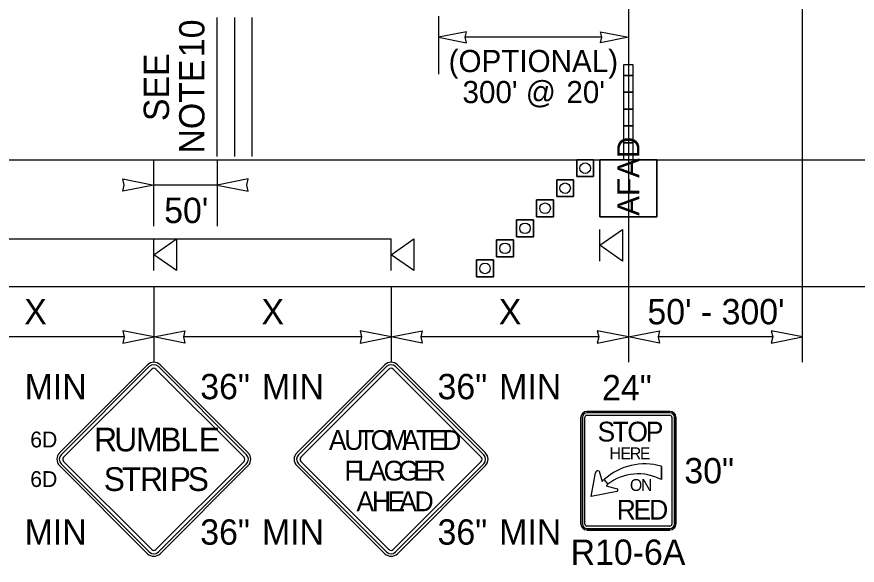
# Model space of a CAD drawing. Extents: x 99999.1 to 100095.7, y 99995 to 100010.7.
# Drawn here: x 100002.344 to 100005, y 100004.851 to 100006.584 of the extents above; entities that cross this region are included whole.
import ezdxf

# ---------------------------------------------------------------- set-up
doc = ezdxf.new("R2010")
doc.units = 0
for name, color, linetype in [('RD_ED_ShoulderPavedEdge', 7, 'Continuous'), ('RD_MK_LineEdgeWhite', 7, 'Continuous'), ('TR_SN_ConstructionSigns', 7, 'Continuous'), ('TR_WZ_AFAD', 7, 'Continuous'), ('TR_WZ_PortableSignMountBlk-Org', 7, 'Continuous'), ('TR_WZ_PortableSignMountBlk-Wht', 7, 'Continuous'), ('TR_WZ_TrafficCone', 7, 'Continuous'), ('TR_WZ_WorkZoneDetails', 7, 'Continuous'), ('TR_WZ_WorkZoneTextCurrent', 7, 'Continuous')]:
    doc.layers.add(name, color=color, linetype=linetype)

msp = doc.modelspace()

# ---------------------------------------------------------------- linework, layer by layer
at = {"layer": 'RD_ED_ShoulderPavedEdge'}
msp.add_line((100000.1076, 100005.7323), (100015.6424, 100005.7323), dxfattribs=at)
at = {"layer": 'RD_MK_LineEdgeWhite'}
msp.add_line((100000.1076, 100006.1323), (100015.6424, 100006.1323), dxfattribs=at)
at = {"layer": 'TR_SN_ConstructionSigns'}
for p, q in [((100002.7568, 100005.4841), (100002.4783, 100005.2057)), ((100002.7623, 100005.4786), (100002.4839, 100005.2001)), ((100002.4916, 100005.1924), (100002.77, 100005.4708)), ((100002.7833, 100005.4708), (100003.0617, 100005.1924)), ((100003.0694, 100005.2001), (100002.791, 100005.4786)), ((100003.075, 100005.2057), (100002.7965, 100005.4841)), ((100003.5068, 100005.4841), (100003.2283, 100005.2057)), ((100003.5123, 100005.4786), (100003.2339, 100005.2001)), ((100003.2416, 100005.1924), (100003.52, 100005.4708)), ((100003.5333, 100005.4708), (100003.8117, 100005.1924)), ((100003.8194, 100005.2001), (100003.541, 100005.4786)), ((100003.825, 100005.2057), (100003.5465, 100005.4841)), ((100004.4079, 100005.3373), (100004.1454, 100005.3373)), ((100004.1454, 100005.3373), (100004.4079, 100005.3373)), ((100004.4079, 100005.3373), (100004.1454, 100005.3373)), ((100004.1454, 100005.3373), (100004.4079, 100005.3373)), ((100004.4079, 100005.3326), (100004.1454, 100005.3326)), ((100004.1267, 100005.3186), (100004.1267, 100004.9811)), ((100004.1267, 100004.9811), (100004.1267, 100005.3186)), ((100004.1267, 100005.3186), (100004.1267, 100004.9811)), ((100004.1267, 100004.9811), (100004.1267, 100005.3186)), ((100004.1313, 100005.3186), (100004.1313, 100004.9811)), ((100004.1392, 100004.9811), (100004.1392, 100005.3186)), ((100004.1454, 100005.3248), (100004.4079, 100005.3248)), ((100004.4142, 100005.3186), (100004.4142, 100004.9811)), ((100004.422, 100004.9811), (100004.422, 100005.3186)), ((100004.4267, 100004.9811), (100004.4267, 100005.3186)), ((100004.4267, 100005.3186), (100004.4267, 100004.9811)), ((100004.4267, 100004.9811), (100004.4267, 100005.3186)), ((100004.4267, 100005.3186), (100004.4267, 100004.9811)), ((100002.4839, 100005.1714), (100002.7623, 100004.893)), ((100002.77, 100004.9007), (100002.4916, 100005.1792)), ((100003.0617, 100005.1792), (100002.7833, 100004.9007)), ((100002.791, 100004.893), (100003.0694, 100005.1714)), ((100003.2339, 100005.1714), (100003.5123, 100004.893)), ((100003.52, 100004.9007), (100003.2416, 100005.1792)), ((100003.8117, 100005.1792), (100003.5333, 100004.9007)), ((100003.541, 100004.893), (100003.8194, 100005.1714)), ((100002.4783, 100005.1659), (100002.7568, 100004.8875)), ((100002.7965, 100004.8875), (100003.075, 100005.1659)), ((100003.2283, 100005.1659), (100003.5068, 100004.8875)), ((100003.5465, 100004.8875), (100003.825, 100005.1659)), ((100004.1595, 100005.0686), (100004.1731, 100005.143)), ((100004.1839, 100005.1479), (100004.1933, 100005.1154)), ((100004.3816, 100005.1635), (100004.3813, 100005.1216)), ((100004.3813, 100005.1216), (100004.3816, 100005.1635)), ((100004.1933, 100005.1154), (100004.1996, 100005.1218)), ((100004.1996, 100005.1218), (100004.2113, 100005.1069)), ((100004.1996, 100005.1218), (100004.2113, 100005.1069)), ((100004.2113, 100005.1069), (100004.2066, 100005.1021)), ((100004.2066, 100005.1021), (100004.2408, 100005.0929)), ((100004.2406, 100005.0837), (100004.1595, 100005.0686)), ((100004.4079, 100004.9748), (100004.1454, 100004.9748)), ((100004.1454, 100004.967), (100004.4079, 100004.967)), ((100004.1454, 100004.9623), (100004.4079, 100004.9623)), ((100004.4079, 100004.9623), (100004.1454, 100004.9623)), ((100004.1454, 100004.9623), (100004.4079, 100004.9623)), ((100004.4079, 100004.9623), (100004.1454, 100004.9623))]:
    msp.add_line(p, q, dxfattribs=at)
for centre, radius, start, end in [((100002.7767, 100005.4642), 0.0281, 45, 135), ((100003.5267, 100005.4642), 0.0281, 45, 135), ((100002.7767, 100005.4642), 0.0203, 45, 135), ((100002.7767, 100005.4642), 0.00937, 45, 135), ((100003.5267, 100005.4642), 0.0203, 45, 135), ((100003.5267, 100005.4642), 0.00937, 45, 135), ((100004.1454, 100005.3186), 0.0187, 90, 180), ((100004.1454, 100005.3186), 0.0187, 90, 180), ((100004.1454, 100005.3186), 0.0187, 90, 180), ((100004.1454, 100005.3186), 0.0187, 90, 180), ((100004.1454, 100005.3186), 0.0141, 90, 180), ((100004.4079, 100005.3186), 0.0187, 0, 90), ((100004.4079, 100005.3186), 0.0187, 0, 90), ((100004.4079, 100005.3186), 0.0187, 0, 90), ((100004.4079, 100005.3186), 0.0187, 0, 90), ((100004.4079, 100005.3186), 0.0141, 0, 90), ((100004.1454, 100005.3186), 0.00625, 90, 180), ((100004.4079, 100005.3186), 0.00625, 0, 90), ((100002.4982, 100005.1858), 0.0281, 135, 225), ((100002.4982, 100005.1858), 0.0203, 135, 225), ((100003.0551, 100005.1858), 0.0203, 315, 45), ((100003.0551, 100005.1858), 0.0281, 315, 45), ((100003.2482, 100005.1858), 0.0281, 135, 225), ((100003.2482, 100005.1858), 0.0203, 135, 225), ((100003.8051, 100005.1858), 0.0203, 315, 45), ((100003.8051, 100005.1858), 0.0281, 315, 45), ((100002.4982, 100005.1858), 0.00937, 135, 225), ((100003.0551, 100005.1858), 0.00937, 315, 45), ((100003.2482, 100005.1858), 0.00937, 135, 225), ((100003.8051, 100005.1858), 0.00937, 315, 45), ((100004.3279, 100004.9804), 0.1909, 73.6434, 132.2131), ((100004.3279, 100004.9804), 0.1909, 73.6434, 132.2131), ((100004.3078, 100004.981), 0.1586, 62.4149, 127.4769), ((100004.3078, 100004.981), 0.1586, 62.4149, 127.4769), ((100004.1454, 100004.9811), 0.0187, 180, 270), ((100004.1454, 100004.9811), 0.0187, 180, 270), ((100004.1454, 100004.9811), 0.0187, 180, 270), ((100004.1454, 100004.9811), 0.0187, 180, 270), ((100004.1454, 100004.9811), 0.0141, 180, 270), ((100004.1454, 100004.9811), 0.00625, 180, 270), ((100004.4079, 100004.9811), 0.0187, 270, 0), ((100004.4079, 100004.9811), 0.0187, 270, 0), ((100004.4079, 100004.9811), 0.0187, 270, 0), ((100004.4079, 100004.9811), 0.0141, 270, 0), ((100004.4079, 100004.9811), 0.00625, 270, 0), ((100004.4079, 100004.9811), 0.0187, 270, 0), ((100002.7767, 100004.9074), 0.0281, 225, 315), ((100002.7767, 100004.9074), 0.0203, 225, 315), ((100002.7767, 100004.9074), 0.00937, 225, 315), ((100003.5267, 100004.9074), 0.0281, 225, 315), ((100003.5267, 100004.9074), 0.0203, 225, 315), ((100003.5267, 100004.9074), 0.00937, 225, 315)]:
    msp.add_arc(centre, radius, start, end, dxfattribs=at)
for centre, major_axis, ratio, start_param, end_param in [((100004.1795, 100005.1431), (-0.00647, -0.00009), 0.989437, 3.962549, 6.283185), ((100004.2384, 100005.0883), (-0.0046, 0.00239), 0.999053, 2.490568, 4.712389)]:
    msp.add_ellipse(centre, major_axis=major_axis, ratio=ratio, start_param=start_param, end_param=end_param, dxfattribs=at)
at = {"layer": 'TR_WZ_AFAD'}
for p, q in [((100004.2916, 100006.399), (100004.2916, 100006.4323)), ((100004.2616, 100006.399), (100004.2616, 100006.3457)), ((100004.2616, 100006.399), (100004.2766, 100006.399)), ((100004.2766, 100006.399), (100004.2916, 100006.399)), ((100004.2916, 100006.3457), (100004.2916, 100006.399)), ((100004.2616, 100006.3457), (100004.2616, 100006.2923)), ((100004.2766, 100006.3457), (100004.2616, 100006.3457)), ((100004.2916, 100006.3457), (100004.2766, 100006.3457)), ((100004.2916, 100006.2923), (100004.2916, 100006.3457)), ((100004.2616, 100006.2923), (100004.2616, 100006.239)), ((100004.2616, 100006.2923), (100004.2766, 100006.2923)), ((100004.2766, 100006.2923), (100004.2916, 100006.2923)), ((100004.2916, 100006.239), (100004.2916, 100006.2923)), ((100004.2766, 100006.239), (100004.2616, 100006.239)), ((100004.2616, 100006.239), (100004.2616, 100006.1857)), ((100004.2916, 100006.239), (100004.2766, 100006.239)), ((100004.2916, 100006.1857), (100004.2916, 100006.239)), ((100004.2616, 100006.1857), (100004.2616, 100006.1323)), ((100004.1866, 100005.9523), (100004.1866, 100006.1323)), ((100004.1866, 100006.1323), (100004.3666, 100006.1323)), ((100004.27, 100006.1323), (100004.1866, 100006.1323)), ((100004.1866, 100006.1323), (100004.1866, 100005.9523)), ((100004.2616, 100006.1323), (100004.27, 100006.1323)), ((100004.27, 100006.1323), (100004.2766, 100006.1323)), ((100004.3666, 100006.1323), (100004.3666, 100005.9523)), ((100004.3666, 100005.9523), (100004.3666, 100006.1323)), ((100004.3666, 100005.9523), (100004.1866, 100005.9523)), ((100004.1866, 100005.9523), (100004.3666, 100005.9523))]:
    msp.add_line(p, q, dxfattribs=at)
for points in [[(100004.2916, 100006.4323), (100004.2616, 100006.4323), (100004.2616, 100006.399)], [(100004.2916, 100006.1323), (100004.2916, 100006.4323), (100004.2616, 100006.4323), (100004.2616, 100006.1323)], [(100004.2916, 100006.399), (100004.2766, 100006.399), (100004.2616, 100006.399)], [(100004.2616, 100006.3457), (100004.2766, 100006.3457), (100004.2916, 100006.3457)], [(100004.2916, 100006.2923), (100004.2766, 100006.2923), (100004.2616, 100006.2923)], [(100004.2616, 100006.239), (100004.2766, 100006.239), (100004.2916, 100006.239)], [(100004.2916, 100006.1857), (100004.2766, 100006.1857), (100004.2616, 100006.1857)], [(100004.2616, 100006.1857), (100004.2766, 100006.1857), (100004.2916, 100006.1857)], [(100004.2766, 100006.1323), (100004.2833, 100006.1323), (100004.2916, 100006.1323), (100004.2916, 100006.1857)], [(100004.3666, 100006.1323), (100004.2833, 100006.1323), (100004.27, 100006.1323)]]:
    msp.add_lwpolyline(points, dxfattribs=at)
at = {"layer": 'TR_WZ_PortableSignMountBlk-Org'}
for p, q in [((100002.7767, 100005.7824), (100002.7767, 100005.8824)), ((100003.5267, 100005.7824), (100003.5267, 100005.8824))]:
    msp.add_line(p, q, dxfattribs=at)
for points in [[(100002.7767, 100005.8323), (100002.8485, 100005.8824), (100002.8485, 100005.7824)], [(100003.5267, 100005.8323), (100003.5985, 100005.8824), (100003.5985, 100005.7824)]]:
    msp.add_lwpolyline(points, close=True, dxfattribs=at)
at = {"layer": 'TR_WZ_PortableSignMountBlk-Wht'}
msp.add_line((100004.1867, 100005.8123), (100004.1867, 100005.9123), dxfattribs=at)
msp.add_lwpolyline([(100004.1867, 100005.8622), (100004.2585, 100005.9123), (100004.2585, 100005.8123)], close=True, dxfattribs=at)
at = {"layer": 'TR_WZ_TrafficCone'}
for points in [[(100004.1133, 100006.1323), (100004.1667, 100006.1323), (100004.1667, 100006.079), (100004.1133, 100006.079), (100004.1133, 100006.1323)], [(100004.1133, 100006.079), (100004.1667, 100006.079), (100004.1667, 100006.1323), (100004.1133, 100006.1323), (100004.1133, 100006.079)], [(100004.05, 100006.069), (100004.1033, 100006.069), (100004.1033, 100006.0157), (100004.05, 100006.0157), (100004.05, 100006.069)], [(100004.05, 100006.0157), (100004.1033, 100006.0157), (100004.1033, 100006.069), (100004.05, 100006.069), (100004.05, 100006.0157)], [(100003.9867, 100006.0057), (100004.04, 100006.0057), (100004.04, 100005.9523), (100003.9867, 100005.9523), (100003.9867, 100006.0057)], [(100003.9867, 100005.9523), (100004.04, 100005.9523), (100004.04, 100006.0057), (100003.9867, 100006.0057), (100003.9867, 100005.9523)], [(100003.9767, 100005.9423), (100003.9233, 100005.9423), (100003.9233, 100005.889), (100003.9767, 100005.889), (100003.9767, 100005.9423)], [(100003.9767, 100005.889), (100003.9233, 100005.889), (100003.9233, 100005.9423), (100003.9767, 100005.9423), (100003.9767, 100005.889)], [(100003.9133, 100005.879), (100003.86, 100005.879), (100003.86, 100005.8257), (100003.9133, 100005.8257), (100003.9133, 100005.879)], [(100003.9133, 100005.8257), (100003.86, 100005.8257), (100003.86, 100005.879), (100003.9133, 100005.879), (100003.9133, 100005.8257)], [(100003.85, 100005.8157), (100003.7967, 100005.8157), (100003.7967, 100005.7623), (100003.85, 100005.7623), (100003.85, 100005.8157)], [(100003.85, 100005.7623), (100003.7967, 100005.7623), (100003.7967, 100005.8157), (100003.85, 100005.8157), (100003.85, 100005.7623)]]:
    msp.add_lwpolyline(points, dxfattribs=at)
for centre in [(100004.14, 100006.1057), (100004.0767, 100006.0423), (100004.0133, 100005.979), (100003.95, 100005.9157), (100003.8867, 100005.8523), (100003.8233, 100005.789)]:
    msp.add_circle(centre, 0.0167, dxfattribs=at)
at = {"layer": 'TR_WZ_WorkZoneDetails'}
for p, q in [((100004.2767, 100008.7991), (100004.2767, 100005.4923)), ((100004.8267, 100005.4923), (100004.8267, 100007.7323)), ((100002.9767, 100006.1423), (100002.9767, 100006.5823)), ((100003.0323, 100006.1423), (100003.0323, 100006.5823)), ((100003.0872, 100006.1423), (100003.0872, 100006.5823)), ((100003.6767, 100006.5857), (100003.6767, 100006.4023)), ((100004.1923, 100006.5193), (100003.761, 100006.5193)), ((100002.7767, 100005.9223), (100002.7767, 100006.1323)), ((100002.9767, 100006.1323), (100002.9767, 100005.9223)), ((100002.9767, 100006.0523), (100002.7767, 100006.0523)), ((100000.5267, 100005.8824), (100003.5267, 100005.8824)), ((100002.7767, 100005.7323), (100002.7767, 100005.4923)), ((100003.5267, 100005.7323), (100003.5267, 100005.4923)), ((100002.6829, 100005.5723), (100002.1204, 100005.5723)), ((100003.4329, 100005.5723), (100002.8704, 100005.5723)), ((100004.1829, 100005.5723), (100003.6204, 100005.5723)), ((100004.7329, 100005.5723), (100004.3704, 100005.5723))]:
    msp.add_line(p, q, dxfattribs=at)
for points in [[(100003.6767, 100006.5193), (100003.7651, 100006.502), (100003.761, 100006.5193), (100003.7651, 100006.5367)], [(100004.2767, 100006.5193), (100004.1882, 100006.502), (100004.1923, 100006.5193), (100004.1882, 100006.5367)], [(100002.7767, 100006.0523), (100002.6784, 100006.0331), (100002.6829, 100006.0523), (100002.6784, 100006.0716)], [(100002.9767, 100006.0523), (100003.0749, 100006.0331), (100003.0704, 100006.0523), (100003.0749, 100006.0716)], [(100002.7767, 100005.5723), (100002.6784, 100005.5916), (100002.6829, 100005.5723), (100002.6784, 100005.5531)], [(100002.7767, 100005.5723), (100002.8749, 100005.5916), (100002.8704, 100005.5723), (100002.8749, 100005.5531)], [(100003.5267, 100005.5723), (100003.4284, 100005.5916), (100003.4329, 100005.5723), (100003.4284, 100005.5531)], [(100003.5267, 100005.5723), (100003.6249, 100005.5916), (100003.6204, 100005.5723), (100003.6249, 100005.5531)], [(100004.2767, 100005.5723), (100004.1784, 100005.5916), (100004.1829, 100005.5723), (100004.1784, 100005.5531)], [(100004.2767, 100005.5723), (100004.3749, 100005.5916), (100004.3704, 100005.5723), (100004.3749, 100005.5531)], [(100004.8267, 100005.5723), (100004.7284, 100005.5916), (100004.7329, 100005.5723), (100004.7284, 100005.5531)]]:
    msp.add_lwpolyline(points, close=True, dxfattribs=at)

# ---------------------------------------------------------------- texts
at = {"layer": 'TR_SN_ConstructionSigns'}
for s, p in [('MIN', (100002.3684, 100005.3756)), ('36"', (100002.9234, 100005.3756)), ('MIN', (100003.1184, 100005.3756)), ('36"', (100003.6734, 100005.3756)), ('MIN', (100003.8684, 100005.3756)), ('24"', (100004.1936, 100005.3723)), ('30"', (100004.4536, 100005.1098)), ('MIN', (100002.3684, 100004.916)), ('36"', (100002.9234, 100004.916)), ('MIN', (100003.1184, 100004.916)), ('36"', (100003.6734, 100004.916)), ('MIN', (100003.8684, 100004.916)), ('R10-6A', (100004.094, 100004.8523))]:
    msp.add_text(s, height=0.08, rotation=360, dxfattribs=at).set_placement(p)
for s, height, p in [('S', 0.0625, (100004.1792, 100005.242)), ('T', 0.0625, (100004.2267, 100005.242)), ('O', 0.0625, (100004.2735, 100005.242)), ('P', 0.0625, (100004.3317, 100005.242)), ('R', 0.075, (100002.588, 100005.2108)), ('U', 0.075, (100002.6518, 100005.2108)), ('M', 0.075, (100002.7208, 100005.2108)), ('B', 0.075, (100002.7973, 100005.2108)), ('L', 0.075, (100002.861, 100005.2108)), ('E', 0.075, (100002.9188, 100005.2108)), ('A', 0.0625, (100003.3301, 100005.2155)), ('U', 0.0625, (100003.3788, 100005.2155)), ('T', 0.0625, (100003.4226, 100005.2155)), ('O', 0.0625, (100003.462, 100005.2155)), ('M', 0.0625, (100003.5113, 100005.2155)), ('A', 0.0625, (100003.5613, 100005.2155)), ('T', 0.0625, (100003.6051, 100005.2155)), ('E', 0.0625, (100003.6457, 100005.2155)), ('D', 0.0625, (100003.6882, 100005.2155)), ('6D', 0.05, (100002.3861, 100005.2233)), ('H', 0.0375, (100004.217, 100005.1858)), ('E', 0.0375, (100004.2515, 100005.1858)), ('R', 0.0375, (100004.2812, 100005.1858)), ('E', 0.0375, (100004.313, 100005.1858)), ('F', 0.0625, (100003.3792, 100005.1186)), ('L', 0.0625, (100003.4198, 100005.1186)), ('A', 0.0625, (100003.4554, 100005.1186)), ('G', 0.0625, (100003.5029, 100005.1186)), ('G', 0.0625, (100003.5492, 100005.1186)), ('E', 0.0625, (100003.5967, 100005.1186)), ('R', 0.0625, (100003.6392, 100005.1186)), ('6D', 0.05, (100002.3861, 100005.0983)), ('S', 0.075, (100002.6184, 100005.0858)), ('T', 0.075, (100002.6754, 100005.0858)), ('R', 0.075, (100002.7332, 100005.0858)), ('I', 0.075, (100002.7969, 100005.0858)), ('P', 0.075, (100002.8269, 100005.0858)), ('S', 0.075, (100002.8839, 100005.0858)), ('O', 0.0375, (100004.2815, 100005.0858)), ('N', 0.0375, (100004.3164, 100005.0858)), ('A', 0.0625, (100003.4173, 100005.0217)), ('H', 0.0625, (100003.466, 100005.0217)), ('E', 0.0625, (100003.5148, 100005.0217)), ('A', 0.0625, (100003.5523, 100005.0217)), ('D', 0.0625, (100003.601, 100005.0217)), ('R', 0.0625, (100004.2399, 100004.9951)), ('E', 0.0625, (100004.293, 100004.9951)), ('D', 0.0625, (100004.3424, 100004.9951))]:
    msp.add_text(s, height=height, dxfattribs=at).set_placement(p)
at = {"layer": 'TR_WZ_AFAD'}
msp.add_text('AFAD', height=0.07, rotation=90, dxfattribs=at).set_placement((100004.3116, 100005.9553))
at = {"layer": 'TR_WZ_WorkZoneDetails'}
for s, p in [('10', (100002.9367, 100006.4566)), ('SEE', (100002.8247, 100006.2544)), ('NOTE', (100002.9367, 100006.1518))]:
    msp.add_text(s, height=0.08, rotation=90, dxfattribs=at).set_placement(p)
at = {"layer": 'TR_WZ_WorkZoneTextCurrent'}
for s, height, p in [('(OPTIONAL)', 0.07, (100003.7085, 100006.4093)), ("300' @", 0.07, (100003.7523, 100006.3113)), ("20'", 0.07, (100004.0807, 100006.3113)), ("50'", 0.08, (100002.8094, 100005.9323))]:
    msp.add_text(s, height=height, dxfattribs=at).set_placement(p)
for s, p in [('X', (100002.3669, 100005.6123)), ('X', (100003.1169, 100005.6123)), ('X', (100003.8669, 100005.6123)), ("50' - 300'", (100004.3369, 100005.6123))]:
    msp.add_text(s, height=0.08, rotation=360, dxfattribs=at).set_placement(p)

doc.saveas('drawing.dxf')
